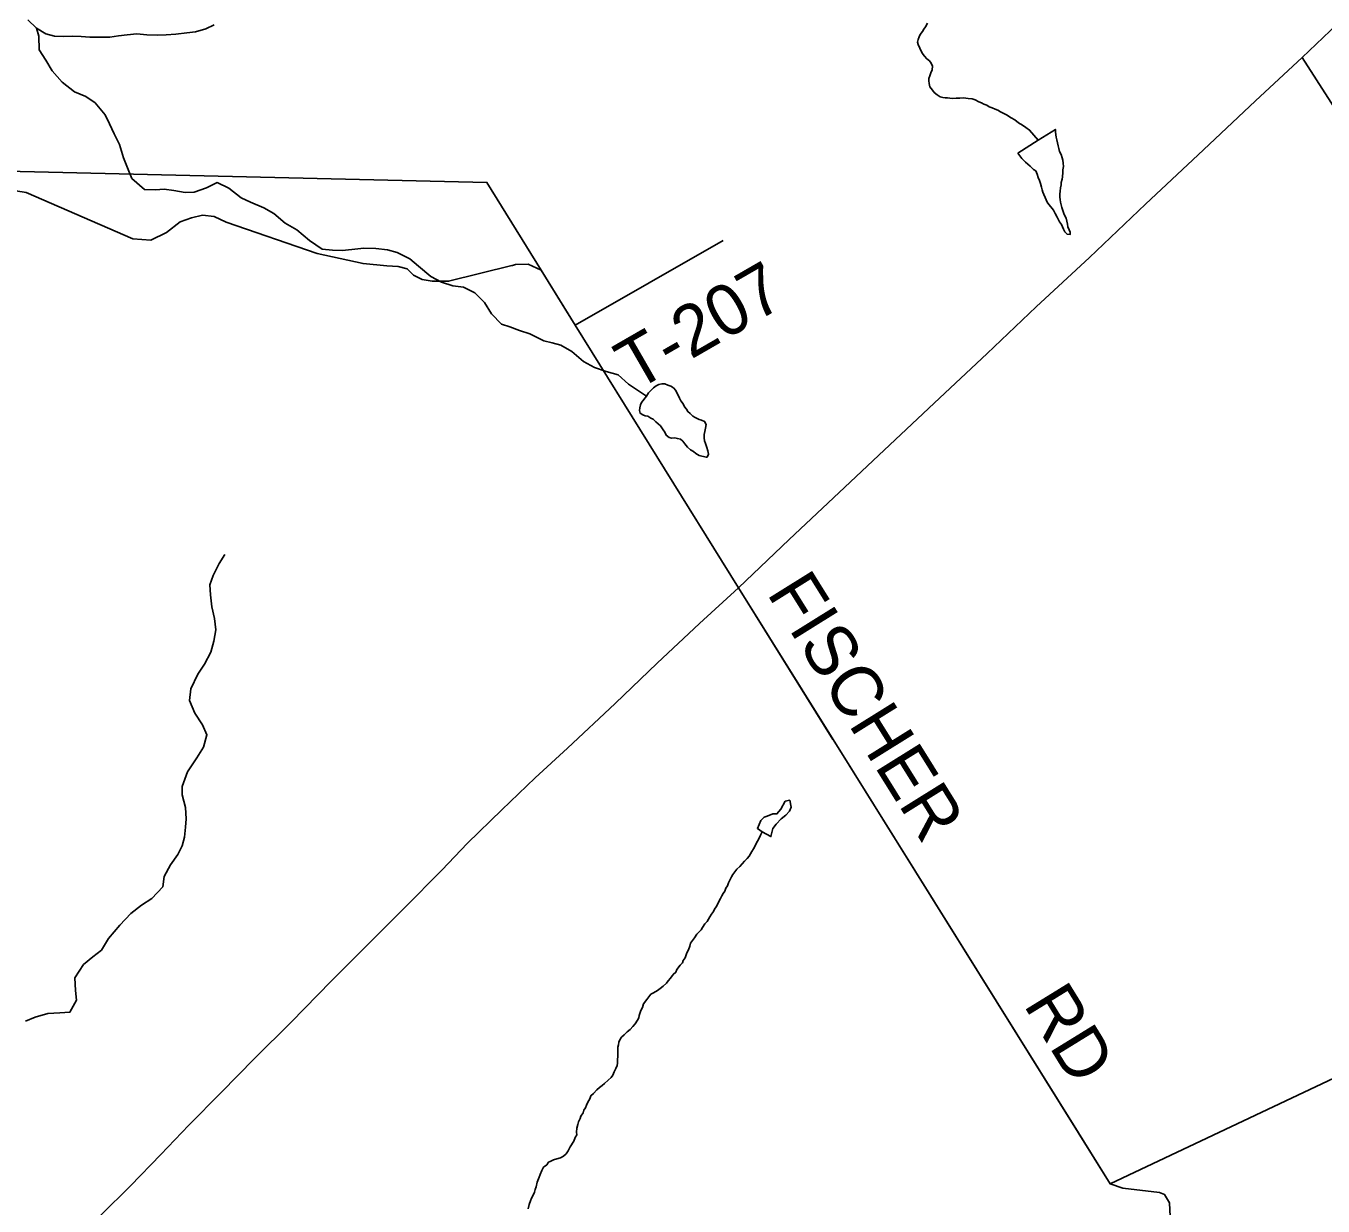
# Model space of a CAD drawing. Extents: x 1310247 to 1664935, y 284496 to 704931.
# Drawn here: x 1532830 to 1540499, y 496300 to 503277 of the extents above; entities that cross this region are included whole.
import ezdxf

# ---------------------------------------------------------------- set-up
doc = ezdxf.new("R2010")
doc.units = 0
for name, color, linetype in [('GM_X_Adjacent_County', 7, 'Continuous'), ('GM_X_City_Street', 7, 'Continuous'), ('GM_X_County_Subdivision_Text', 7, 'Continuous'), ('GM_X_Interstate_Shield', 7, 'Continuous'), ('GM_X_Minor_River', 7, 'Continuous'), ('GM_X_Minor_River_Text', 7, 'Continuous'), ('GM_X_Township_Subdivision', 7, 'Continuous')]:
    doc.layers.add(name, color=color, linetype=linetype)

msp = doc.modelspace()

# ---------------------------------------------------------------- linework, layer by layer
at = {"layer": 'GM_X_Adjacent_County'}
for points in [[(1546686.4, 513989.1), (1546297.7, 509605.7), (1545822.1, 504298.4), (1545798, 504043.7), (1545352.6, 499330.6), (1543391.6, 498392.7), (1539239.6, 496432), (1537601.9, 499058.4), (1537044, 499954.2), (1536077.6, 501508.1), (1535875.9, 501832.4), (1535555.7, 502352.1), (1532125.8, 502432.2), (1530754.3, 502475.8), (1526460.8, 502612), (1526364.4, 502615.1), (1523999.8, 502690.1), (1523132.5, 502717.6), (1519529.8, 502831.9)], [(1532125.8, 502432.2), (1535555.7, 502352.1), (1535875.9, 501832.4), (1536077.6, 501508.1), (1537044, 499954.2), (1537601.9, 499058.4), (1539239.6, 496432), (1543391.6, 498392.7)]]:
    msp.add_lwpolyline(points, dxfattribs=at)
at = {"layer": 'GM_X_City_Street'}
msp.add_lwpolyline([(1532840.7, 503313.6), (1532892, 503264.3), (1532947.7, 503231), (1532999.7, 503215.9), (1533050.1, 503214.8), (1533106.5, 503217.7), (1533156.8, 503214.6), (1533207, 503211.6), (1533267.4, 503210.3), (1533325.8, 503211.1), (1533376.3, 503218.1), (1533428.8, 503225), (1533485.3, 503229.8), (1533545.6, 503224.6), (1533606, 503223.3), (1533658.3, 503224.2), (1533716.8, 503229), (1533781.4, 503235.7), (1533831.9, 503242.7), (1533892.7, 503259.5), (1533943.5, 503284.5)], dxfattribs=at)
at = {"layer": 'GM_X_County_Subdivision_Text'}
for points in [[(1543440, 498317.1), (1543391.6, 498392.6), (1540375.6, 503089.9)], [(1532719.9, 502310.6), (1532832.1, 502292.8), (1533462.5, 502018.3), (1533568.8, 502010.6), (1533661.9, 502055.3), (1533741.3, 502118.3), (1533808, 502143.3), (1533874.5, 502158.3), (1533942.6, 502151.2), (1534014.4, 502118), (1534551.5, 501932.6), (1534823.5, 501872.6), (1534963.6, 501859.6), (1535031.6, 501854.6), (1535083.6, 501840.6), (1535121.6, 501804.6), (1535173.6, 501778.6), (1535232.6, 501768.6), (1535328.7, 501767.5), (1535702.4, 501860.2), (1535707.1, 501861.6)], [(1536951.4, 502008.3), (1536077.6, 501508.2)], [(1535707.1, 501861.6), (1535723.8, 501866.9), (1535800.2, 501869.7), (1535875.9, 501832.4), (1536016.6, 501606.3)], [(1536016.6, 501606.3), (1536077.6, 501508.2), (1537044, 499954.2), (1537601.5, 499058.9)], [(1537601.5, 499058.9), (1537601.9, 499058.4), (1539052.4, 496732.1)], [(1539052.4, 496732.1), (1539239.6, 496432), (1539315.5, 496406.7), (1539532, 496379.3), (1539562, 496368.8), (1539591.3, 496318.2), (1539617.3, 495800.4), (1539604.7, 495640.2), (1539524.5, 495396.8), (1539431.3, 495089.4), (1539382.6, 494799.4), (1539389.1, 494580.7), (1539393.5, 494344), (1539387.5, 494223.8), (1539361.8, 494115.9), (1539382.1, 494005.3), (1539973.5, 492348.4)]]:
    msp.add_lwpolyline(points, dxfattribs=at)
at = {"layer": 'GM_X_Interstate_Shield'}
msp.add_lwpolyline([(1533273.2, 496246.7), (1533447.4, 496420.5), (1533627.8, 496604.1), (1533793.8, 496778), (1533984.7, 496971.4), (1534181.7, 497172.6), (1534397.3, 497387.3), (1534633.7, 497629.5), (1534857.6, 497852), (1535066.9, 498060.9), (1535288.8, 498285.5), (1535440.3, 498445.8), (1535643.3, 498642.8), (1535840, 498831.9), (1536032.3, 499007.2), (1536313.7, 499272.2), (1536562.2, 499510.1), (1536812.5, 499743.9), (1537044, 499954.2), (1537342.2, 500240.8), (1537638.1, 500519.5), (1537905, 500768.9), (1538200.9, 501047.6), (1538513.3, 501339.9), (1538803.1, 501616.7), (1539117.6, 501909), (1539448.7, 502222.8), (1539792.2, 502544.3), (1540100.5, 502834.7), (1540375.6, 503089.9), (1540624.1, 503327.7)], dxfattribs=at)
at = {"layer": 'GM_X_Minor_River'}
for points in [[(1538861.9, 502248.8), (1538868.1, 502235.5), (1538877.8, 502221.3), (1538889.5, 502206.9), (1538905.1, 502188.5), (1538914.6, 502168.2), (1538928.1, 502145.8), (1538941.5, 502119.4), (1538953.2, 502103.1), (1538958.9, 502088.9), (1538964.5, 502074.7), (1538972.2, 502060.5), (1538985.9, 502046.1), (1539003.9, 502043.7), (1539004.3, 502057.7), (1538998.6, 502071.9), (1538991, 502090.1), (1538987.4, 502104.3), (1538980.2, 502140.5), (1538968.7, 502162.9), (1538963.2, 502181.1), (1538955.7, 502203.3), (1538950.1, 502219.5), (1538946.4, 502235.7), (1538944.9, 502251.8), (1538943.2, 502265.8), (1538943.6, 502281.9), (1538944, 502299.9), (1538946.6, 502319.9), (1538951, 502337.9), (1538951.4, 502351.9), (1538955.9, 502371.9), (1538958.2, 502385.8), (1538960.9, 502409.9), (1538961.3, 502425.9), (1538963.8, 502445.9), (1538962.3, 502466), (1538960.7, 502484.1), (1538957, 502498.2), (1538951.5, 502516.4), (1538941.9, 502534.7), (1538936.3, 502552.9), (1538932.7, 502569), (1538929.1, 502585.2), (1538925.5, 502603.3), (1538921.9, 502619.5), (1538920.3, 502633.5), (1538916.7, 502651.7), (1538917, 502665.7), (1538815.3, 502600.9)], [(1538815.3, 502600.9), (1538695.3, 502524.4)], [(1538695.3, 502524.4), (1538706.2, 502508.3), (1538717.9, 502494), (1538739.4, 502471.4), (1538767, 502448.6), (1538786.5, 502428.1), (1538800.4, 502419.8), (1538808, 502401.5), (1538815.5, 502381.3), (1538823.1, 502363), (1538828.7, 502344.8), (1538834.2, 502324.6), (1538837.8, 502308.5), (1538841.5, 502294.4), (1538861.9, 502248.8)], [(1536851.3, 500728), (1536857.6, 500727.2), (1536866.1, 500745), (1536862.6, 500765.2), (1536855, 500785.4), (1536847.6, 500807.7), (1536841.9, 500823.8), (1536840.4, 500841.9), (1536840.9, 500862), (1536843.3, 500880), (1536847.9, 500899.9), (1536852.4, 500919.9), (1536842.8, 500938.2), (1536824.9, 500946.6), (1536811, 500951), (1536787.1, 500961.6), (1536773.3, 500970), (1536757.6, 500986.4), (1536743.8, 500996.7), (1536736.1, 501011), (1536724.5, 501025.3), (1536714.9, 501043.6), (1536701.2, 501060), (1536693.6, 501076.2), (1536687.9, 501090.4), (1536678.3, 501108.7), (1536672.7, 501122.8), (1536658.9, 501137.2), (1536643.1, 501147.6), (1536625.2, 501154.1), (1536607.3, 501160.5), (1536589.2, 501161), (1536571.1, 501157.4), (1536556.8, 501149.7), (1536540.5, 501138.1), (1536526, 501124.4), (1536511.6, 501108.7), (1536499, 501088.9)], [(1536499, 501088.9), (1536470, 501051.5), (1536463.6, 501037.6), (1536459.1, 501019.7), (1536456.7, 501003.7), (1536462.3, 500987.5), (1536478.2, 500977.1), (1536492.1, 500972.7), (1536506.1, 500970.4), (1536523.9, 500957.9), (1536537.8, 500951.6), (1536553.5, 500937.1), (1536567.2, 500924.8), (1536581, 500912.4), (1536598.5, 500889.9), (1536608.2, 500875.6), (1536615.8, 500857.4), (1536633.6, 500844.9), (1536647.5, 500840.6), (1536665.6, 500842.1), (1536681.6, 500837.7), (1536699.5, 500833.3), (1536713.4, 500822.9), (1536725, 500806.6), (1536740.6, 500786.2), (1536758.3, 500771.7), (1536776.1, 500761.2), (1536789.8, 500748.9), (1536809.7, 500738.3), (1536851.3, 500728)], [(1537183, 498511.7), (1537234.8, 498484.6), (1537245.9, 498532.6), (1537266.5, 498558.3), (1537295.4, 498589.8), (1537322, 498611.4), (1537344.7, 498635.1), (1537355.2, 498659), (1537345.9, 498699.3), (1537319.6, 498693.8), (1537292.5, 498646.1), (1537269.8, 498618.5), (1537245.6, 498618.9)], [(1537245.6, 498618.9), (1537213, 498605.5), (1537194.8, 498599.8), (1537174.2, 498580.2), (1537155.2, 498532.3), (1537183, 498511.7)]]:
    msp.add_lwpolyline(points, dxfattribs=at)
at = {"layer": 'GM_X_Minor_River_Text'}
for points in [[(1538815.3, 502600.9), (1538764.3, 502661.4), (1538742.5, 502675.9), (1538722.8, 502690.5), (1538699.1, 502705.1), (1538677.4, 502721.6), (1538655.6, 502734.2), (1538627.9, 502750.9), (1538608.1, 502761.5), (1538592.2, 502769.8), (1538576.4, 502778.3), (1538560.4, 502784.7), (1538542.6, 502793.1), (1538524.7, 502799.6), (1538510.8, 502807.9), (1538492.9, 502814.4), (1538479, 502822.7), (1538463.1, 502829.1), (1538443.3, 502839.6), (1538425.4, 502846.1), (1538401.3, 502848.7), (1538387.3, 502851), (1538373.3, 502851.4), (1538351.1, 502849.9), (1538329.1, 502850.4), (1538310.9, 502848.9), (1538292.9, 502849.3), (1538278.9, 502851.6), (1538264.8, 502852), (1538250.8, 502854.3), (1538234.8, 502858.7), (1538217, 502869.2), (1538199.3, 502883.7), (1538189.6, 502897.9), (1538174, 502916.4), (1538170.5, 502936.5), (1538168.9, 502952.6), (1538169.2, 502966.6), (1538173.7, 502982.6), (1538180.2, 503000.5), (1538188.6, 503018.3), (1538189.1, 503038.4), (1538181.6, 503056.6), (1538171.9, 503070.9), (1538156.1, 503083.3), (1538142.4, 503097.7), (1538128.8, 503116.1), (1538115.5, 503146.5), (1538106, 503166.8), (1538102.3, 503180.9), (1538104.7, 503196.9), (1538111.1, 503212.8), (1538117.5, 503226.7), (1538130, 503244.5), (1538138.4, 503258.3), (1538148.8, 503272.1), (1538161.4, 503293.9)], [(1532892, 503264.3), (1532905.5, 503217.4), (1532907.9, 503135), (1532947, 503074), (1532984, 503011), (1533043.2, 502945.6), (1533116.7, 502888), (1533184.7, 502860.5), (1533238.4, 502823.3), (1533297.4, 502751.9), (1533324.6, 502699.2), (1533351.6, 502638.4), (1533382.6, 502575.6), (1533407.3, 502496.8), (1533430.3, 502438.1), (1533455.3, 502375.3), (1533530.6, 502309.6), (1533595.1, 502308.4), (1533647.6, 502311.4), (1533703.9, 502304.3), (1533772.2, 502292.9), (1533824.6, 502293.9), (1533897.7, 502320.6), (1533960.8, 502351.5), (1534028.7, 502318), (1534102.2, 502260.4), (1534158.1, 502235.2), (1534236.1, 502201.5), (1534295.9, 502168.3), (1534363.3, 502110.7), (1534431.1, 502071.3), (1534506.4, 502009.5), (1534582, 501957.9), (1534642.4, 501950.7), (1534698.8, 501949.6), (1534757.3, 501954.5), (1534828.1, 501963.1), (1534898.6, 501961.8), (1534967, 501954.4), (1535025.1, 501937.2), (1535099, 501899.6), (1535150.5, 501856.5), (1535224, 501796.8), (1535287.8, 501761.4), (1535353.9, 501740.1), (1535416.2, 501732.8), (1535484.1, 501699.4), (1535541.4, 501642.1), (1535582.4, 501575), (1535641.7, 501513.6), (1535691.8, 501498.6), (1535747.8, 501477.4), (1535809.9, 501456.1), (1535891.8, 501416.4), (1535941.9, 501403.3), (1535992.1, 501390.3), (1536057.8, 501352.9), (1536127.2, 501293.3), (1536191, 501258), (1536261.1, 501234.5), (1536331.3, 501215.1), (1536392.7, 501159.6), (1536499, 501088.9)], [(1533754.2, 498429.7), (1533767.3, 498481.7), (1533772.5, 498539.8), (1533777.5, 498589.9), (1533772.8, 498656.2), (1533754.1, 498730.9), (1533753.1, 498781.1), (1533785, 498866.9), (1533841.1, 498950.1), (1533880.7, 499013.6), (1533900.2, 499085.5), (1533873.2, 499144.3), (1533828.2, 499213.4), (1533797.4, 499288.3), (1533804.8, 499358.5), (1533846.8, 499444), (1533886.3, 499503.5), (1533924, 499575), (1533941.4, 499638.9), (1533952.8, 499707), (1533944.1, 499773.4), (1533929.3, 499842), (1533920.7, 499914.5), (1533917.8, 499972.7), (1533937, 500028.6), (1533972.7, 500098.2), (1534006, 500151.8)], [(1536236.2, 497012.4), (1536250.6, 497024.1), (1536273.1, 497043.6), (1536289.6, 497059.3), (1536300, 497073.1), (1536308.5, 497093), (1536317.1, 497112.8), (1536325.5, 497130.7), (1536327.9, 497144.7), (1536328.5, 497168.7), (1536328.9, 497182.7), (1536329.3, 497200.8), (1536329.7, 497216.8), (1536330.3, 497238.9), (1536332.6, 497252.9), (1536335, 497268.9), (1536341.4, 497282.8), (1536351.8, 497298.6), (1536366.3, 497312.3), (1536384.8, 497329.9), (1536403.2, 497343.5), (1536417.7, 497361.2), (1536432.2, 497376.9), (1536446.8, 497398.6), (1536453.1, 497412.5), (1536455.5, 497426.5), (1536466.3, 497456.3), (1536474.8, 497474.1), (1536481.3, 497496.1), (1536500.1, 497521.7), (1536512.5, 497537.5), (1536525, 497553.2), (1536541.2, 497560.8), (1536563.7, 497574.3), (1536580, 497586), (1536598.5, 497599.6), (1536617, 497617.2), (1536627.4, 497631), (1536641.8, 497646.7), (1536656.4, 497668.4), (1536672.8, 497682), (1536679.3, 497697.9), (1536698, 497723.6), (1536712.4, 497737.3), (1536716.8, 497751.2), (1536727.2, 497767), (1536738, 497796.8), (1536746.5, 497814.7), (1536755.1, 497836.5), (1536759.5, 497854.5), (1536772, 497870.2), (1536782.4, 497886), (1536797, 497907.8), (1536821.8, 497933.3), (1536830.1, 497947.1), (1536844.7, 497968.8), (1536857.1, 497982.6), (1536865.5, 497996.4), (1536873.9, 498010.2), (1536884.3, 498026), (1536894.8, 498041.8), (1536901.2, 498055.7), (1536911.6, 498069.5), (1536917.9, 498083.4), (1536928.5, 498105.2), (1536936.9, 498119.1), (1536945.3, 498134.9), (1536951.7, 498148.8), (1536962.1, 498162.6), (1536968.6, 498180.5), (1536977, 498194.3), (1536983.4, 498210.2), (1536991.8, 498226.1), (1537002.3, 498245.9), (1537008.7, 498259.8), (1537021.2, 498275.5), (1537033.6, 498291.3), (1537050.1, 498306.9), (1537064.5, 498322.6), (1537079, 498338.3), (1537093.5, 498354), (1537105.9, 498367.8), (1537114.2, 498381.6), (1537122.6, 498395.5), (1537131, 498411.3), (1537139.4, 498425.1), (1537147.9, 498443), (1537156.3, 498456.8), (1537164.8, 498474.7), (1537173.3, 498492.6), (1537183, 498511.7)], [(1532826.5, 497393.5), (1532885.4, 497416.4), (1532958.4, 497439.1), (1533031.1, 497441.7), (1533089.6, 497446.6), (1533129.3, 497518.1), (1533122.4, 497574.5), (1533119.8, 497648.8), (1533169.8, 497728.2), (1533225.1, 497773.3), (1533276.3, 497812.5), (1533318, 497881.9), (1533384.1, 497961), (1533449.9, 498030), (1533513.4, 498078.9), (1533574.7, 498117.9), (1533638.5, 498187), (1533647.8, 498249), (1533685.4, 498316.6), (1533727, 498378), (1533754.2, 498429.7)], [(1535800.1, 496284.6), (1535804.7, 496308.6), (1535813.3, 496330.5), (1535819.8, 496346.4), (1535828.2, 496364.2), (1535836.7, 496382.1), (1535841.1, 496398), (1535847.6, 496413.9), (1535852.3, 496441.9), (1535865.1, 496471.7), (1535869.5, 496487.6), (1535880.1, 496509.4), (1535890.6, 496529.2), (1535909.1, 496544.8), (1535919.5, 496558.6), (1535933.7, 496566.3), (1535950, 496573.9), (1535968.2, 496579.5), (1535990.5, 496585), (1536008.8, 496594.6), (1536023.2, 496608.3), (1536035.7, 496626), (1536048.3, 496649.8), (1536069.3, 496683.4), (1536077.8, 496705.3), (1536086.3, 496721.1), (1536084.7, 496737.2), (1536087.3, 496761.2), (1536093.9, 496783.1), (1536096.2, 496797.1), (1536106.8, 496816.9), (1536111.1, 496830.9), (1536123.7, 496850.6), (1536128.1, 496866.6), (1536138.5, 496880.4), (1536144.9, 496896.3), (1536151.4, 496914.2), (1536163.9, 496933.9), (1536170.4, 496951.8), (1536184.8, 496965.5), (1536205.4, 496987.1), (1536221.8, 497000.8), (1536236.2, 497012.4)]]:
    msp.add_lwpolyline(points, dxfattribs=at)

# ---------------------------------------------------------------- texts
at = {"layer": 'GM_X_Township_Subdivision'}
for s, rotation, p in [('T-207', 29.95416, (1536432.9, 501114.2)), ('FISCHER', 301.93479, (1537206.3, 499924.3)), ('RD', 301.6394, (1538724.1, 497491.2))]:
    msp.add_text(s, height=300, rotation=rotation, dxfattribs=at).set_placement(p)

doc.saveas('drawing.dxf')
